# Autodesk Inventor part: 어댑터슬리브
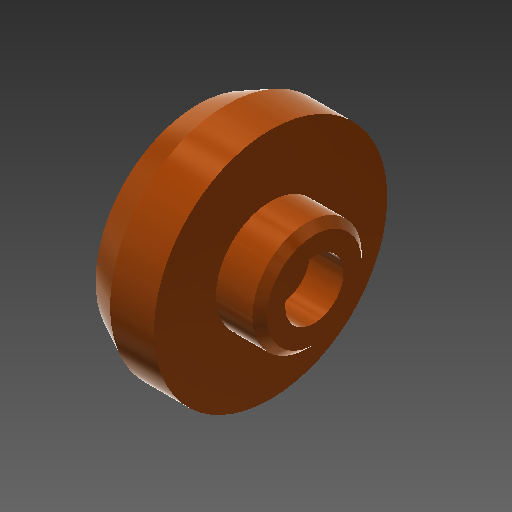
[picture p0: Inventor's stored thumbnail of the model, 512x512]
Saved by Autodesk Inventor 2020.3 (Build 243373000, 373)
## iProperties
Created: 2016-06
Part Number: 어댑터슬리브
Material: 강철, 탄소
Document SubType Name: Modeling
Designer: mduedu
Density: 7.87 g/cm^3
Appearance: 매끄러움 - 연한 주황색
Author: mduedu
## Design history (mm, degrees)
sketch "스케치2"
  geometry: L1 (0, 0)-(0, 14); L2 (0, 14)-(-4, 16); L3 (-4, 16)-(-10, 16); L4 (-10, 16)-(-10, 7.5); L5 (-10, 7.5)-(-16, 7.5); L6 (-16, 7.5)-(-16, 0); L7 (-16, 0)-(0, 0)
  constraints: 14 end point, 4 parallel, 1 perpendicular, 1 vertical
  dimensions: "d0" = 32 diameter of L3 L7; "d2" = 28 diameter of L1.end L7; "d3" = 6 distance of L2.end L3.end; "d4" = 6 distance of L4.end L5.end; "d5" = 15 diameter of L5 L7; "d6" = 16 distance between parallel lines of L6 L1
revolve "회전1" sketch "스케치2" stored, may be unused: angle "d7" = 90 deg
sketch "스케치3"
  geometry: L1 (-16, -7.5)-(-16, 7.5) reference; L2 (-16, 7.5)-(-10, 7.5) reference; L3 (-10, 7.5)-(-10, 16) reference; L4 (-10, 16)-(-4, 16) reference; L5 (-4, 16)-(0, 14) reference; L6 (0, 14)-(0, -14) reference; L7 (0, -14)-(-4, -16) reference; L8 (-4, -16)-(-10, -16) reference; L9 (-10, -16)-(-10, -7.5) reference; L10 (-10, -7.5)-(-16, -7.5) reference; L11 (0, 10)-(-5, 10); L12 (-5, 10)-(-5, 8); L13 (-5, 8)-(-7, 6); L14 (-7, 6)-(-7, 0); L15 (-7, 0)-(0, 0); L16 (0, 10)-(0, 0)
  constraints: 12 end point, 3 parallel, 2 perpendicular, 1 point on line
  dimensions: "d8" = 20 diameter of L11 L15; "d10" = 16 diameter of L12.end L15; "d11" = 12 diameter of L13.end L15; "d12" = 9 distance between parallel lines of L14 L1; "d13" = 2 distance between parallel lines of L12 L14
revolve "회전2" sketch "스케치3" stored, may be unused: angle "d14" = 90 deg
chamfer "모따기1" distance "d15" = 1; stored, may be unused: second distance "d16" = 2, angle "d17" = 45 deg
sketch "스케치4"
  geometry: 2 further points
  constraints: 1 coincident
sketch "스케치5"
  geometry: 1 further point
hole "구멍1" sketch "스케치5" at (0, 0) diameter "d18" = 4.5; stored, may be unused: countersink angle "d22" = 90 deg, drill point angle "d24" = 0 deg; dims "d19" = 6, "d20" = 8, "d21" = 4.6, "d23" = 8
node "솔리드1"
node "절단 모서리 투영1"
